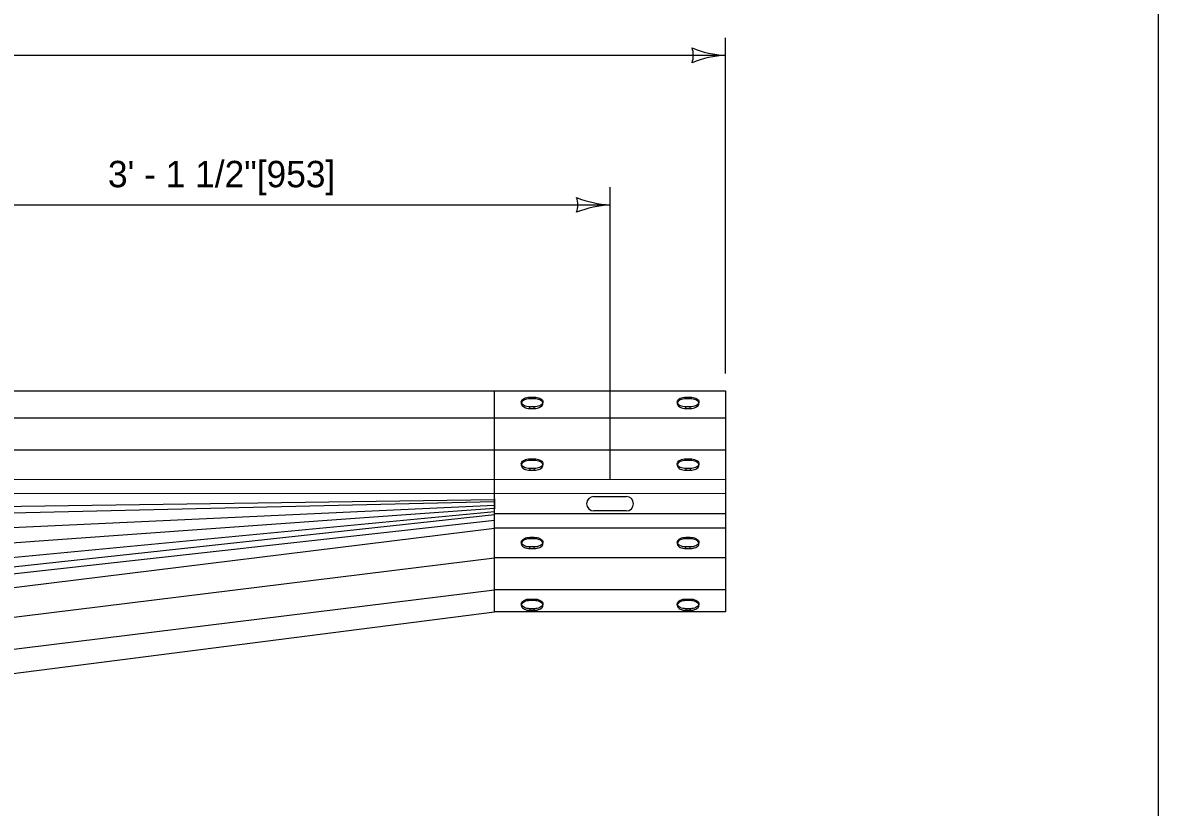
# Model space of a CAD drawing. Extents: x 49991 to 50160, y 49948 to 50051.
# Drawn here: x 50014.17 to 50016.75, y 49992.536 to 49994.317 of the extents above; entities that cross this region are included whole.
import ezdxf

# ---------------------------------------------------------------- set-up
doc = ezdxf.new("R2010")
doc.units = 0
for name, color, linetype in [('Level 1', 7, 'Continuous'), ('Level 2', 7, 'Continuous'), ('Level 3', 7, 'Continuous')]:
    doc.layers.add(name, color=color, linetype=linetype)

msp = doc.modelspace()

# ---------------------------------------------------------------- linework, layer by layer
at = {"layer": 'Level 1'}
for p, q in [((50012.234, 49993.4814), (50015.7668, 49993.4812)), ((50015.2419, 49992.9795), (50015.2419, 49993.4812)), ((50015.3222, 49993.4673), (50015.3321, 49993.4673)), ((50015.3222, 49993.4637), (50015.3222, 49993.4673)), ((50015.3321, 49993.4637), (50015.3222, 49993.4637)), ((50015.3321, 49993.4637), (50015.3321, 49993.4673)), ((50015.6766, 49993.4637), (50015.6766, 49993.4673)), ((50015.6766, 49993.4673), (50015.6864, 49993.4673)), ((50015.6864, 49993.4637), (50015.6766, 49993.4637)), ((50015.6864, 49993.4637), (50015.6864, 49993.4673)), ((50015.7668, 49993.4812), (50015.7668, 49993.4738)), ((50015.7668, 49993.4738), (50015.7668, 49993.471)), ((50015.7668, 49993.471), (50015.7668, 49993.4206)), ((50015.3025, 49993.4563), (50015.3025, 49993.4527)), ((50015.3321, 49993.4453), (50015.3222, 49993.4453)), ((50015.3222, 49993.4416), (50015.3222, 49993.4453)), ((50015.3222, 49993.4416), (50015.3321, 49993.4416)), ((50015.3321, 49993.4416), (50015.3321, 49993.4453)), ((50015.3518, 49993.4527), (50015.3518, 49993.4563)), ((50015.6569, 49993.4563), (50015.6569, 49993.4527)), ((50015.6864, 49993.4453), (50015.6766, 49993.4453)), ((50015.6766, 49993.4416), (50015.6766, 49993.4453)), ((50015.6766, 49993.4416), (50015.6864, 49993.4416)), ((50015.6864, 49993.4416), (50015.6864, 49993.4453)), ((50015.7061, 49993.4527), (50015.7061, 49993.4563)), ((50012.6417, 49993.4206), (50015.7668, 49993.4206)), ((50015.7668, 49993.4206), (50015.7668, 49993.3481)), ((50012.6417, 49993.3481), (50015.7668, 49993.3478)), ((50015.7668, 49993.3481), (50015.7668, 49993.2808)), ((50015.3025, 49993.3161), (50015.3025, 49993.3125)), ((50015.3222, 49993.3271), (50015.3321, 49993.3271)), ((50015.3222, 49993.3271), (50015.3222, 49993.3235)), ((50015.3321, 49993.3235), (50015.3222, 49993.3235)), ((50015.3222, 49993.3051), (50015.3222, 49993.3014)), ((50015.3321, 49993.3051), (50015.3222, 49993.3051)), ((50015.3321, 49993.3271), (50015.3321, 49993.3235)), ((50015.3321, 49993.3051), (50015.3321, 49993.3014)), ((50015.3518, 49993.3125), (50015.3518, 49993.3161)), ((50015.6569, 49993.3161), (50015.6569, 49993.3125)), ((50015.6766, 49993.3271), (50015.6864, 49993.3271)), ((50015.6766, 49993.3271), (50015.6766, 49993.3235)), ((50015.6864, 49993.3235), (50015.6766, 49993.3235)), ((50015.6766, 49993.3051), (50015.6766, 49993.3014)), ((50015.6864, 49993.3051), (50015.6766, 49993.3051)), ((50015.6864, 49993.3271), (50015.6864, 49993.3235)), ((50015.6864, 49993.3051), (50015.6864, 49993.3014)), ((50015.7061, 49993.3125), (50015.7061, 49993.3161)), ((50012.6417, 49993.2803), (50015.7668, 49993.2808)), ((50015.3222, 49993.3014), (50015.3321, 49993.3014)), ((50015.6766, 49993.3014), (50015.6864, 49993.3014)), ((50015.7668, 49993.2808), (50015.7668, 49993.2482)), ((50015.2419, 49993.2294), (50012.6417, 49993.1687)), ((50013.9757, 49993.2172), (50015.2419, 49993.2352)), ((50013.9811, 49993.2491), (50015.7668, 49993.2485)), ((50015.2419, 49993.2367), (50015.2419, 49993.2321)), ((50015.2419, 49993.2321), (50015.2419, 49993.2275)), ((50015.2419, 49993.2275), (50015.2419, 49993.223)), ((50015.4674, 49993.2417), (50015.5412, 49993.2417)), ((50015.7668, 49993.2482), (50015.7668, 49993.2023)), ((50012.6417, 49993.1011), (50015.2419, 49993.2221)), ((50015.2419, 49993.2146), (50012.6417, 49993.0283)), ((50012.6417, 49992.9608), (50015.2419, 49993.2073)), ((50013.9883, 49993.0651), (50015.2419, 49993.201)), ((50015.2419, 49993.223), (50015.2419, 49993.2184)), ((50015.2419, 49993.2184), (50015.2419, 49993.2138)), ((50015.7668, 49993.2023), (50015.2419, 49993.2023)), ((50015.5412, 49993.2088), (50015.4674, 49993.2088)), ((50015.7668, 49993.2023), (50015.7668, 49993.1697)), ((50013.9906, 49993.0485), (50015.2419, 49993.1879)), ((50012.6417, 49992.8492), (50015.2419, 49993.1697)), ((50015.7668, 49993.1697), (50015.2419, 49993.1697)), ((50015.3222, 49993.1491), (50015.3321, 49993.1491)), ((50015.3222, 49993.1454), (50015.3222, 49993.1491)), ((50015.3321, 49993.1454), (50015.3321, 49993.1491)), ((50015.6766, 49993.1491), (50015.6864, 49993.1491)), ((50015.6766, 49993.1454), (50015.6766, 49993.1491)), ((50015.6864, 49993.1454), (50015.6864, 49993.1491)), ((50015.7668, 49993.1697), (50015.7668, 49993.1024)), ((50015.3025, 49993.138), (50015.3025, 49993.1344)), ((50015.3321, 49993.1454), (50015.3222, 49993.1454)), ((50015.3321, 49993.127), (50015.3222, 49993.127)), ((50015.3222, 49993.1234), (50015.3222, 49993.127)), ((50015.3222, 49993.1234), (50015.3321, 49993.1234)), ((50015.3321, 49993.1234), (50015.3321, 49993.127)), ((50015.3518, 49993.1344), (50015.3518, 49993.138)), ((50015.6569, 49993.138), (50015.6569, 49993.1344)), ((50015.6864, 49993.1454), (50015.6766, 49993.1454)), ((50015.6864, 49993.127), (50015.6766, 49993.127)), ((50015.6766, 49993.1234), (50015.6766, 49993.127)), ((50015.6766, 49993.1234), (50015.6864, 49993.1234)), ((50015.6864, 49993.1234), (50015.6864, 49993.127)), ((50015.7061, 49993.1344), (50015.7061, 49993.138)), ((50012.6417, 49992.7816), (50015.2419, 49993.1024)), ((50015.7668, 49993.1024), (50015.2419, 49993.1024)), ((50015.7668, 49993.1024), (50015.7668, 49993.0299)), ((50012.6417, 49992.7088), (50015.2419, 49993.0299)), ((50015.7668, 49993.0299), (50015.2419, 49993.0299)), ((50015.7668, 49993.0299), (50015.7668, 49992.9795)), ((50015.3025, 49992.9978), (50015.3025, 49992.9942)), ((50015.3222, 49993.0089), (50015.3321, 49993.0089)), ((50015.3222, 49993.0089), (50015.3222, 49993.0052)), ((50015.3321, 49993.0052), (50015.3222, 49993.0052)), ((50015.3321, 49993.0089), (50015.3321, 49993.0052)), ((50015.3518, 49992.9942), (50015.3518, 49992.9978)), ((50015.6569, 49992.9978), (50015.6569, 49992.9942)), ((50015.6766, 49993.0089), (50015.6864, 49993.0089)), ((50015.6766, 49993.0089), (50015.6766, 49993.0052)), ((50015.6864, 49993.0052), (50015.6766, 49993.0052)), ((50015.6864, 49993.0089), (50015.6864, 49993.0052)), ((50015.7061, 49992.9942), (50015.7061, 49992.9978)), ((50012.6417, 49992.6481), (50015.2419, 49992.9795)), ((50015.7668, 49992.9795), (50015.2419, 49992.9795)), ((50015.3222, 49992.9868), (50015.3222, 49992.9832)), ((50015.3321, 49992.9868), (50015.3222, 49992.9868)), ((50015.3222, 49992.9832), (50015.3321, 49992.9832)), ((50015.3321, 49992.9868), (50015.3321, 49992.9832)), ((50015.6766, 49992.9868), (50015.6766, 49992.9832)), ((50015.6864, 49992.9868), (50015.6766, 49992.9868)), ((50015.6766, 49992.9832), (50015.6864, 49992.9832)), ((50015.6864, 49992.9868), (50015.6864, 49992.9832))]:
    msp.add_line(p, q, dxfattribs=at)
msp.add_lwpolyline([(49999.3835, 49998.9992), (50016.7501, 49998.9992), (50016.7501, 49987.7988), (49999.3835, 49987.7988)], close=True, dxfattribs=at)
for points in [[(50015.3222, 49993.4453), (50015.3188, 49993.4454), (50015.3155, 49993.4459), (50015.3124, 49993.4467), (50015.3096, 49993.4478), (50015.3072, 49993.4492), (50015.3052, 49993.4508), (50015.3037, 49993.4525), (50015.3028, 49993.4544), (50015.3025, 49993.4563), (50015.3028, 49993.4582), (50015.3037, 49993.4601), (50015.3052, 49993.4618), (50015.3072, 49993.4634), (50015.3096, 49993.4647), (50015.3124, 49993.4658), (50015.3155, 49993.4666), (50015.3188, 49993.4671), (50015.3222, 49993.4673)], [(50015.3222, 49993.4637), (50015.3188, 49993.4635), (50015.3155, 49993.463), (50015.3124, 49993.4622), (50015.3096, 49993.4611), (50015.3072, 49993.4597), (50015.3052, 49993.4582), (50015.3037, 49993.4564), (50015.3028, 49993.4546), (50015.3028, 49993.4545)], [(50015.3321, 49993.4673), (50015.3355, 49993.4671), (50015.3388, 49993.4666), (50015.3419, 49993.4658), (50015.3447, 49993.4647), (50015.3472, 49993.4634), (50015.3491, 49993.4618), (50015.3506, 49993.4601), (50015.3515, 49993.4582), (50015.3518, 49993.4563), (50015.3515, 49993.4544), (50015.3506, 49993.4525), (50015.3491, 49993.4508), (50015.3472, 49993.4492), (50015.3447, 49993.4478), (50015.3419, 49993.4467), (50015.3388, 49993.4459), (50015.3355, 49993.4454), (50015.3321, 49993.4453)], [(50015.3515, 49993.4545), (50015.3515, 49993.4546), (50015.3506, 49993.4564), (50015.3491, 49993.4582), (50015.3472, 49993.4597), (50015.3447, 49993.4611), (50015.3419, 49993.4622), (50015.3388, 49993.463), (50015.3355, 49993.4635), (50015.3321, 49993.4637)], [(50015.6766, 49993.4453), (50015.6731, 49993.4454), (50015.6698, 49993.4459), (50015.6667, 49993.4467), (50015.6639, 49993.4478), (50015.6615, 49993.4492), (50015.6595, 49993.4508), (50015.6581, 49993.4525), (50015.6572, 49993.4544), (50015.6569, 49993.4563), (50015.6572, 49993.4582), (50015.6581, 49993.4601), (50015.6595, 49993.4618), (50015.6615, 49993.4634), (50015.6639, 49993.4647), (50015.6667, 49993.4658), (50015.6698, 49993.4666), (50015.6731, 49993.4671), (50015.6766, 49993.4673)], [(50015.6766, 49993.4637), (50015.6731, 49993.4635), (50015.6698, 49993.463), (50015.6667, 49993.4622), (50015.6639, 49993.4611), (50015.6615, 49993.4597), (50015.6595, 49993.4582), (50015.6581, 49993.4564), (50015.6572, 49993.4546), (50015.6571, 49993.4545)], [(50015.6864, 49993.4673), (50015.6898, 49993.4671), (50015.6931, 49993.4666), (50015.6963, 49993.4658), (50015.6991, 49993.4647), (50015.7015, 49993.4634), (50015.7035, 49993.4618), (50015.7049, 49993.4601), (50015.7058, 49993.4582), (50015.7061, 49993.4563), (50015.7058, 49993.4544), (50015.7049, 49993.4525), (50015.7035, 49993.4508), (50015.7015, 49993.4492), (50015.6991, 49993.4478), (50015.6963, 49993.4467), (50015.6931, 49993.4459), (50015.6898, 49993.4454), (50015.6864, 49993.4453)], [(50015.7058, 49993.4545), (50015.7058, 49993.4546), (50015.7049, 49993.4564), (50015.7035, 49993.4582), (50015.7015, 49993.4597), (50015.6991, 49993.4611), (50015.6963, 49993.4622), (50015.6931, 49993.463), (50015.6898, 49993.4635), (50015.6864, 49993.4637)], [(50015.3028, 49993.4545), (50015.3025, 49993.4527), (50015.3028, 49993.4507), (50015.3037, 49993.4489), (50015.3052, 49993.4471), (50015.3072, 49993.4456), (50015.3096, 49993.4442), (50015.3124, 49993.4431), (50015.3155, 49993.4423), (50015.3188, 49993.4418), (50015.3222, 49993.4416)], [(50015.3321, 49993.4416), (50015.3355, 49993.4418), (50015.3388, 49993.4423), (50015.3419, 49993.4431), (50015.3447, 49993.4442), (50015.3472, 49993.4456), (50015.3491, 49993.4471), (50015.3506, 49993.4489), (50015.3515, 49993.4507), (50015.3518, 49993.4527), (50015.3515, 49993.4545)], [(50015.6571, 49993.4545), (50015.6569, 49993.4527), (50015.6572, 49993.4507), (50015.6581, 49993.4489), (50015.6595, 49993.4471), (50015.6615, 49993.4456), (50015.6639, 49993.4442), (50015.6667, 49993.4431), (50015.6698, 49993.4423), (50015.6731, 49993.4418), (50015.6766, 49993.4416)], [(50015.6864, 49993.4416), (50015.6898, 49993.4418), (50015.6931, 49993.4423), (50015.6963, 49993.4431), (50015.6991, 49993.4442), (50015.7015, 49993.4456), (50015.7035, 49993.4471), (50015.7049, 49993.4489), (50015.7058, 49993.4507), (50015.7061, 49993.4527), (50015.7058, 49993.4545)], [(50015.3028, 49993.3143), (50015.3025, 49993.3161), (50015.3028, 49993.318), (50015.3037, 49993.3199), (50015.3052, 49993.3216), (50015.3072, 49993.3232), (50015.3096, 49993.3245), (50015.3124, 49993.3256), (50015.3155, 49993.3264), (50015.3188, 49993.3269), (50015.3222, 49993.3271)], [(50015.3222, 49993.3235), (50015.3188, 49993.3233), (50015.3155, 49993.3228), (50015.3124, 49993.322), (50015.3096, 49993.3209), (50015.3072, 49993.3195), (50015.3052, 49993.318), (50015.3037, 49993.3162), (50015.3028, 49993.3144), (50015.3025, 49993.3125), (50015.3028, 49993.3105), (50015.3037, 49993.3087), (50015.3052, 49993.3069), (50015.3072, 49993.3054), (50015.3096, 49993.304), (50015.3124, 49993.3029), (50015.3155, 49993.3021), (50015.3188, 49993.3016), (50015.3222, 49993.3014)], [(50015.3222, 49993.3051), (50015.3188, 49993.3052), (50015.3155, 49993.3057), (50015.3124, 49993.3065), (50015.3096, 49993.3076), (50015.3072, 49993.309), (50015.3052, 49993.3106), (50015.3037, 49993.3123), (50015.3028, 49993.3142), (50015.3028, 49993.3143)], [(50015.3321, 49993.3271), (50015.3355, 49993.3269), (50015.3388, 49993.3264), (50015.3419, 49993.3256), (50015.3447, 49993.3245), (50015.3472, 49993.3232), (50015.3491, 49993.3216), (50015.3506, 49993.3199), (50015.3515, 49993.318), (50015.3518, 49993.3161), (50015.3515, 49993.3143)], [(50015.3321, 49993.3014), (50015.3355, 49993.3016), (50015.3388, 49993.3021), (50015.3419, 49993.3029), (50015.3447, 49993.304), (50015.3472, 49993.3054), (50015.3491, 49993.3069), (50015.3506, 49993.3087), (50015.3515, 49993.3105), (50015.3518, 49993.3125), (50015.3515, 49993.3144), (50015.3506, 49993.3162), (50015.3491, 49993.318), (50015.3472, 49993.3195), (50015.3447, 49993.3209), (50015.3419, 49993.322), (50015.3388, 49993.3228), (50015.3355, 49993.3233), (50015.3321, 49993.3235)], [(50015.3515, 49993.3143), (50015.3515, 49993.3142), (50015.3506, 49993.3123), (50015.3491, 49993.3106), (50015.3472, 49993.309), (50015.3447, 49993.3076), (50015.3419, 49993.3065), (50015.3388, 49993.3057), (50015.3355, 49993.3052), (50015.3321, 49993.3051)], [(50015.6571, 49993.3143), (50015.6569, 49993.3161), (50015.6572, 49993.318), (50015.6581, 49993.3199), (50015.6595, 49993.3216), (50015.6615, 49993.3232), (50015.6639, 49993.3245), (50015.6667, 49993.3256), (50015.6698, 49993.3264), (50015.6731, 49993.3269), (50015.6766, 49993.3271)], [(50015.6766, 49993.3235), (50015.6731, 49993.3233), (50015.6698, 49993.3228), (50015.6667, 49993.322), (50015.6639, 49993.3209), (50015.6615, 49993.3195), (50015.6595, 49993.318), (50015.6581, 49993.3162), (50015.6572, 49993.3144), (50015.6569, 49993.3125), (50015.6572, 49993.3105), (50015.6581, 49993.3087), (50015.6595, 49993.3069), (50015.6615, 49993.3054), (50015.6639, 49993.304), (50015.6667, 49993.3029), (50015.6698, 49993.3021), (50015.6731, 49993.3016), (50015.6766, 49993.3014)], [(50015.6766, 49993.3051), (50015.6731, 49993.3052), (50015.6698, 49993.3057), (50015.6667, 49993.3065), (50015.6639, 49993.3076), (50015.6615, 49993.309), (50015.6595, 49993.3106), (50015.6581, 49993.3123), (50015.6572, 49993.3142), (50015.6571, 49993.3143)], [(50015.6864, 49993.3271), (50015.6898, 49993.3269), (50015.6931, 49993.3264), (50015.6963, 49993.3256), (50015.6991, 49993.3245), (50015.7015, 49993.3232), (50015.7035, 49993.3216), (50015.7049, 49993.3199), (50015.7058, 49993.318), (50015.7061, 49993.3161), (50015.7058, 49993.3143)], [(50015.6864, 49993.3014), (50015.6898, 49993.3016), (50015.6931, 49993.3021), (50015.6963, 49993.3029), (50015.6991, 49993.304), (50015.7015, 49993.3054), (50015.7035, 49993.3069), (50015.7049, 49993.3087), (50015.7058, 49993.3105), (50015.7061, 49993.3125), (50015.7058, 49993.3144), (50015.7049, 49993.3162), (50015.7035, 49993.318), (50015.7015, 49993.3195), (50015.6991, 49993.3209), (50015.6963, 49993.322), (50015.6931, 49993.3228), (50015.6898, 49993.3233), (50015.6864, 49993.3235)], [(50015.7058, 49993.3143), (50015.7058, 49993.3142), (50015.7049, 49993.3123), (50015.7035, 49993.3106), (50015.7015, 49993.309), (50015.6991, 49993.3076), (50015.6963, 49993.3065), (50015.6931, 49993.3057), (50015.6898, 49993.3052), (50015.6864, 49993.3051)], [(50015.3222, 49993.127), (50015.3188, 49993.1272), (50015.3155, 49993.1277), (50015.3124, 49993.1285), (50015.3096, 49993.1296), (50015.3072, 49993.131), (50015.3052, 49993.1325), (50015.3037, 49993.1343), (50015.3028, 49993.1361), (50015.3025, 49993.138), (50015.3028, 49993.14), (50015.3037, 49993.1418), (50015.3052, 49993.1436), (50015.3072, 49993.1451), (50015.3096, 49993.1465), (50015.3124, 49993.1476), (50015.3155, 49993.1484), (50015.3188, 49993.1489), (50015.3222, 49993.1491)], [(50015.3321, 49993.1491), (50015.3355, 49993.1489), (50015.3388, 49993.1484), (50015.3419, 49993.1476), (50015.3447, 49993.1465), (50015.3472, 49993.1451), (50015.3491, 49993.1436), (50015.3506, 49993.1418), (50015.3515, 49993.14), (50015.3518, 49993.138), (50015.3515, 49993.1361), (50015.3506, 49993.1343), (50015.3491, 49993.1325), (50015.3472, 49993.131), (50015.3447, 49993.1296), (50015.3419, 49993.1285), (50015.3388, 49993.1277), (50015.3355, 49993.1272), (50015.3321, 49993.127)], [(50015.6766, 49993.127), (50015.6731, 49993.1272), (50015.6698, 49993.1277), (50015.6667, 49993.1285), (50015.6639, 49993.1296), (50015.6615, 49993.131), (50015.6595, 49993.1325), (50015.6581, 49993.1343), (50015.6572, 49993.1361), (50015.6569, 49993.138), (50015.6572, 49993.14), (50015.6581, 49993.1418), (50015.6595, 49993.1436), (50015.6615, 49993.1451), (50015.6639, 49993.1465), (50015.6667, 49993.1476), (50015.6698, 49993.1484), (50015.6731, 49993.1489), (50015.6766, 49993.1491)], [(50015.6864, 49993.1491), (50015.6898, 49993.1489), (50015.6931, 49993.1484), (50015.6963, 49993.1476), (50015.6991, 49993.1465), (50015.7015, 49993.1451), (50015.7035, 49993.1436), (50015.7049, 49993.1418), (50015.7058, 49993.14), (50015.7061, 49993.138), (50015.7058, 49993.1361), (50015.7049, 49993.1343), (50015.7035, 49993.1325), (50015.7015, 49993.131), (50015.6991, 49993.1296), (50015.6963, 49993.1285), (50015.6931, 49993.1277), (50015.6898, 49993.1272), (50015.6864, 49993.127)], [(50015.3028, 49993.1362), (50015.3025, 49993.1344), (50015.3028, 49993.1325), (50015.3037, 49993.1306), (50015.3052, 49993.1289), (50015.3072, 49993.1273), (50015.3096, 49993.126), (50015.3124, 49993.1249), (50015.3155, 49993.1241), (50015.3188, 49993.1236), (50015.3222, 49993.1234)], [(50015.3222, 49993.1454), (50015.3188, 49993.1453), (50015.3155, 49993.1448), (50015.3124, 49993.144), (50015.3096, 49993.1429), (50015.3072, 49993.1415), (50015.3052, 49993.1399), (50015.3037, 49993.1382), (50015.3028, 49993.1363), (50015.3028, 49993.1362)], [(50015.3515, 49993.1362), (50015.3515, 49993.1363), (50015.3506, 49993.1382), (50015.3491, 49993.1399), (50015.3472, 49993.1415), (50015.3447, 49993.1429), (50015.3419, 49993.144), (50015.3388, 49993.1448), (50015.3355, 49993.1453), (50015.3321, 49993.1454)], [(50015.3321, 49993.1234), (50015.3355, 49993.1236), (50015.3388, 49993.1241), (50015.3419, 49993.1249), (50015.3447, 49993.126), (50015.3472, 49993.1273), (50015.3491, 49993.1289), (50015.3506, 49993.1306), (50015.3515, 49993.1325), (50015.3518, 49993.1344), (50015.3515, 49993.1362)], [(50015.6571, 49993.1362), (50015.6569, 49993.1344), (50015.6572, 49993.1325), (50015.6581, 49993.1306), (50015.6595, 49993.1289), (50015.6615, 49993.1273), (50015.6639, 49993.126), (50015.6667, 49993.1249), (50015.6698, 49993.1241), (50015.6731, 49993.1236), (50015.6766, 49993.1234)], [(50015.6766, 49993.1454), (50015.6731, 49993.1453), (50015.6698, 49993.1448), (50015.6667, 49993.144), (50015.6639, 49993.1429), (50015.6615, 49993.1415), (50015.6595, 49993.1399), (50015.6581, 49993.1382), (50015.6572, 49993.1363), (50015.6571, 49993.1362)], [(50015.7058, 49993.1362), (50015.7058, 49993.1363), (50015.7049, 49993.1382), (50015.7035, 49993.1399), (50015.7015, 49993.1415), (50015.6991, 49993.1429), (50015.6963, 49993.144), (50015.6931, 49993.1448), (50015.6898, 49993.1453), (50015.6864, 49993.1454)], [(50015.6864, 49993.1234), (50015.6898, 49993.1236), (50015.6931, 49993.1241), (50015.6963, 49993.1249), (50015.6991, 49993.126), (50015.7015, 49993.1273), (50015.7035, 49993.1289), (50015.7049, 49993.1306), (50015.7058, 49993.1325), (50015.7061, 49993.1344), (50015.7058, 49993.1362)], [(50015.3028, 49992.996), (50015.3025, 49992.9978), (50015.3028, 49992.9998), (50015.3037, 49993.0016), (50015.3052, 49993.0034), (50015.3072, 49993.0049), (50015.3096, 49993.0063), (50015.3124, 49993.0074), (50015.3155, 49993.0082), (50015.3188, 49993.0087), (50015.3222, 49993.0089)], [(50015.3222, 49993.0052), (50015.3188, 49993.0051), (50015.3155, 49993.0046), (50015.3124, 49993.0038), (50015.3096, 49993.0027), (50015.3072, 49993.0013), (50015.3052, 49992.9997), (50015.3037, 49992.998), (50015.3028, 49992.9961), (50015.3025, 49992.9942), (50015.3028, 49992.9923), (50015.3037, 49992.9904), (50015.3052, 49992.9887), (50015.3072, 49992.9871), (50015.3096, 49992.9858), (50015.3124, 49992.9847), (50015.3155, 49992.9839), (50015.3188, 49992.9834), (50015.3222, 49992.9832)], [(50015.3222, 49992.9868), (50015.3188, 49992.987), (50015.3155, 49992.9875), (50015.3124, 49992.9883), (50015.3096, 49992.9894), (50015.3072, 49992.9908), (50015.3052, 49992.9923), (50015.3037, 49992.9941), (50015.3028, 49992.9959), (50015.3028, 49992.996)], [(50015.3321, 49993.0089), (50015.3355, 49993.0087), (50015.3388, 49993.0082), (50015.3419, 49993.0074), (50015.3447, 49993.0063), (50015.3472, 49993.0049), (50015.3491, 49993.0034), (50015.3506, 49993.0016), (50015.3515, 49992.9998), (50015.3518, 49992.9978), (50015.3515, 49992.996)], [(50015.3321, 49992.9832), (50015.3355, 49992.9834), (50015.3388, 49992.9839), (50015.3419, 49992.9847), (50015.3447, 49992.9858), (50015.3472, 49992.9871), (50015.3491, 49992.9887), (50015.3506, 49992.9904), (50015.3515, 49992.9923), (50015.3518, 49992.9942), (50015.3515, 49992.9961), (50015.3506, 49992.998), (50015.3491, 49992.9997), (50015.3472, 49993.0013), (50015.3447, 49993.0027), (50015.3419, 49993.0038), (50015.3388, 49993.0046), (50015.3355, 49993.0051), (50015.3321, 49993.0052)], [(50015.3515, 49992.996), (50015.3515, 49992.9959), (50015.3506, 49992.9941), (50015.3491, 49992.9923), (50015.3472, 49992.9908), (50015.3447, 49992.9894), (50015.3419, 49992.9883), (50015.3388, 49992.9875), (50015.3355, 49992.987), (50015.3321, 49992.9868)], [(50015.6571, 49992.996), (50015.6569, 49992.9978), (50015.6572, 49992.9998), (50015.6581, 49993.0016), (50015.6595, 49993.0034), (50015.6615, 49993.0049), (50015.6639, 49993.0063), (50015.6667, 49993.0074), (50015.6698, 49993.0082), (50015.6731, 49993.0087), (50015.6766, 49993.0089)], [(50015.6766, 49993.0052), (50015.6731, 49993.0051), (50015.6698, 49993.0046), (50015.6667, 49993.0038), (50015.6639, 49993.0027), (50015.6615, 49993.0013), (50015.6595, 49992.9997), (50015.6581, 49992.998), (50015.6572, 49992.9961), (50015.6569, 49992.9942), (50015.6572, 49992.9923), (50015.6581, 49992.9904), (50015.6595, 49992.9887), (50015.6615, 49992.9871), (50015.6639, 49992.9858), (50015.6667, 49992.9847), (50015.6698, 49992.9839), (50015.6731, 49992.9834), (50015.6766, 49992.9832)], [(50015.6766, 49992.9868), (50015.6731, 49992.987), (50015.6698, 49992.9875), (50015.6667, 49992.9883), (50015.6639, 49992.9894), (50015.6615, 49992.9908), (50015.6595, 49992.9923), (50015.6581, 49992.9941), (50015.6572, 49992.9959), (50015.6571, 49992.996)], [(50015.6864, 49993.0089), (50015.6898, 49993.0087), (50015.6931, 49993.0082), (50015.6963, 49993.0074), (50015.6991, 49993.0063), (50015.7015, 49993.0049), (50015.7035, 49993.0034), (50015.7049, 49993.0016), (50015.7058, 49992.9998), (50015.7061, 49992.9978), (50015.7058, 49992.996)], [(50015.6864, 49992.9832), (50015.6898, 49992.9834), (50015.6931, 49992.9839), (50015.6963, 49992.9847), (50015.6991, 49992.9858), (50015.7015, 49992.9871), (50015.7035, 49992.9887), (50015.7049, 49992.9904), (50015.7058, 49992.9923), (50015.7061, 49992.9942), (50015.7058, 49992.9961), (50015.7049, 49992.998), (50015.7035, 49992.9997), (50015.7015, 49993.0013), (50015.6991, 49993.0027), (50015.6963, 49993.0038), (50015.6931, 49993.0046), (50015.6898, 49993.0051), (50015.6864, 49993.0052)], [(50015.7058, 49992.996), (50015.7058, 49992.9959), (50015.7049, 49992.9941), (50015.7035, 49992.9923), (50015.7015, 49992.9908), (50015.6991, 49992.9894), (50015.6963, 49992.9883), (50015.6931, 49992.9875), (50015.6898, 49992.987), (50015.6864, 49992.9868)]]:
    msp.add_lwpolyline(points, dxfattribs=at)
for centre, start, end in [((50015.4674, 49993.2252), 90, 270), ((50015.5412, 49993.2252), 270, 90)]:
    msp.add_arc(centre, 0.0164, start, end, dxfattribs=at)
at = {"layer": 'Level 3'}
for p, q in [((50015.7668, 49993.5212), (50015.7668, 49994.2833)), ((50012.1168, 49994.2433), (50015.7668, 49994.2433)), ((50015.5043, 49993.2817), (50015.5043, 49993.9437)), ((50013.9388, 49993.9037), (50015.5043, 49993.9037))]:
    msp.add_line(p, q, dxfattribs=at)
for centre, radius, start, end in [((50015.7759, 49994.4654), 0.2223, 247.456, 267.6395), ((50015.6386, 49994.2433), 0.0548, 342.1388, 17.8612), ((50015.7783, 49994.0106), 0.233, 92.8273, 112.0772), ((50015.5135, 49994.1259), 0.2223, 247.456, 267.6395), ((50015.3761, 49993.9037), 0.0548, 342.1388, 17.8612), ((50015.5158, 49993.671), 0.233, 92.8273, 112.0772)]:
    msp.add_arc(centre, radius, start, end, dxfattribs=at)

# ---------------------------------------------------------------- texts
at = {"layer": 'Level 2'}
msp.add_text('3\' - 1 1/2"[953]', height=0.06, dxfattribs=at).set_placement((50014.3632, 49993.9437))

doc.saveas('drawing.dxf')
